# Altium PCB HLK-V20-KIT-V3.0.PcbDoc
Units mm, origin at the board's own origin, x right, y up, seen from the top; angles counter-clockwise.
Board outline 30 x 34 mm, 2 copper layers (Top Layer, Bottom Layer); 25 components, 30 nets, 128 pads, 85 vias.
Unrouted connection lines stored in the file: 3.
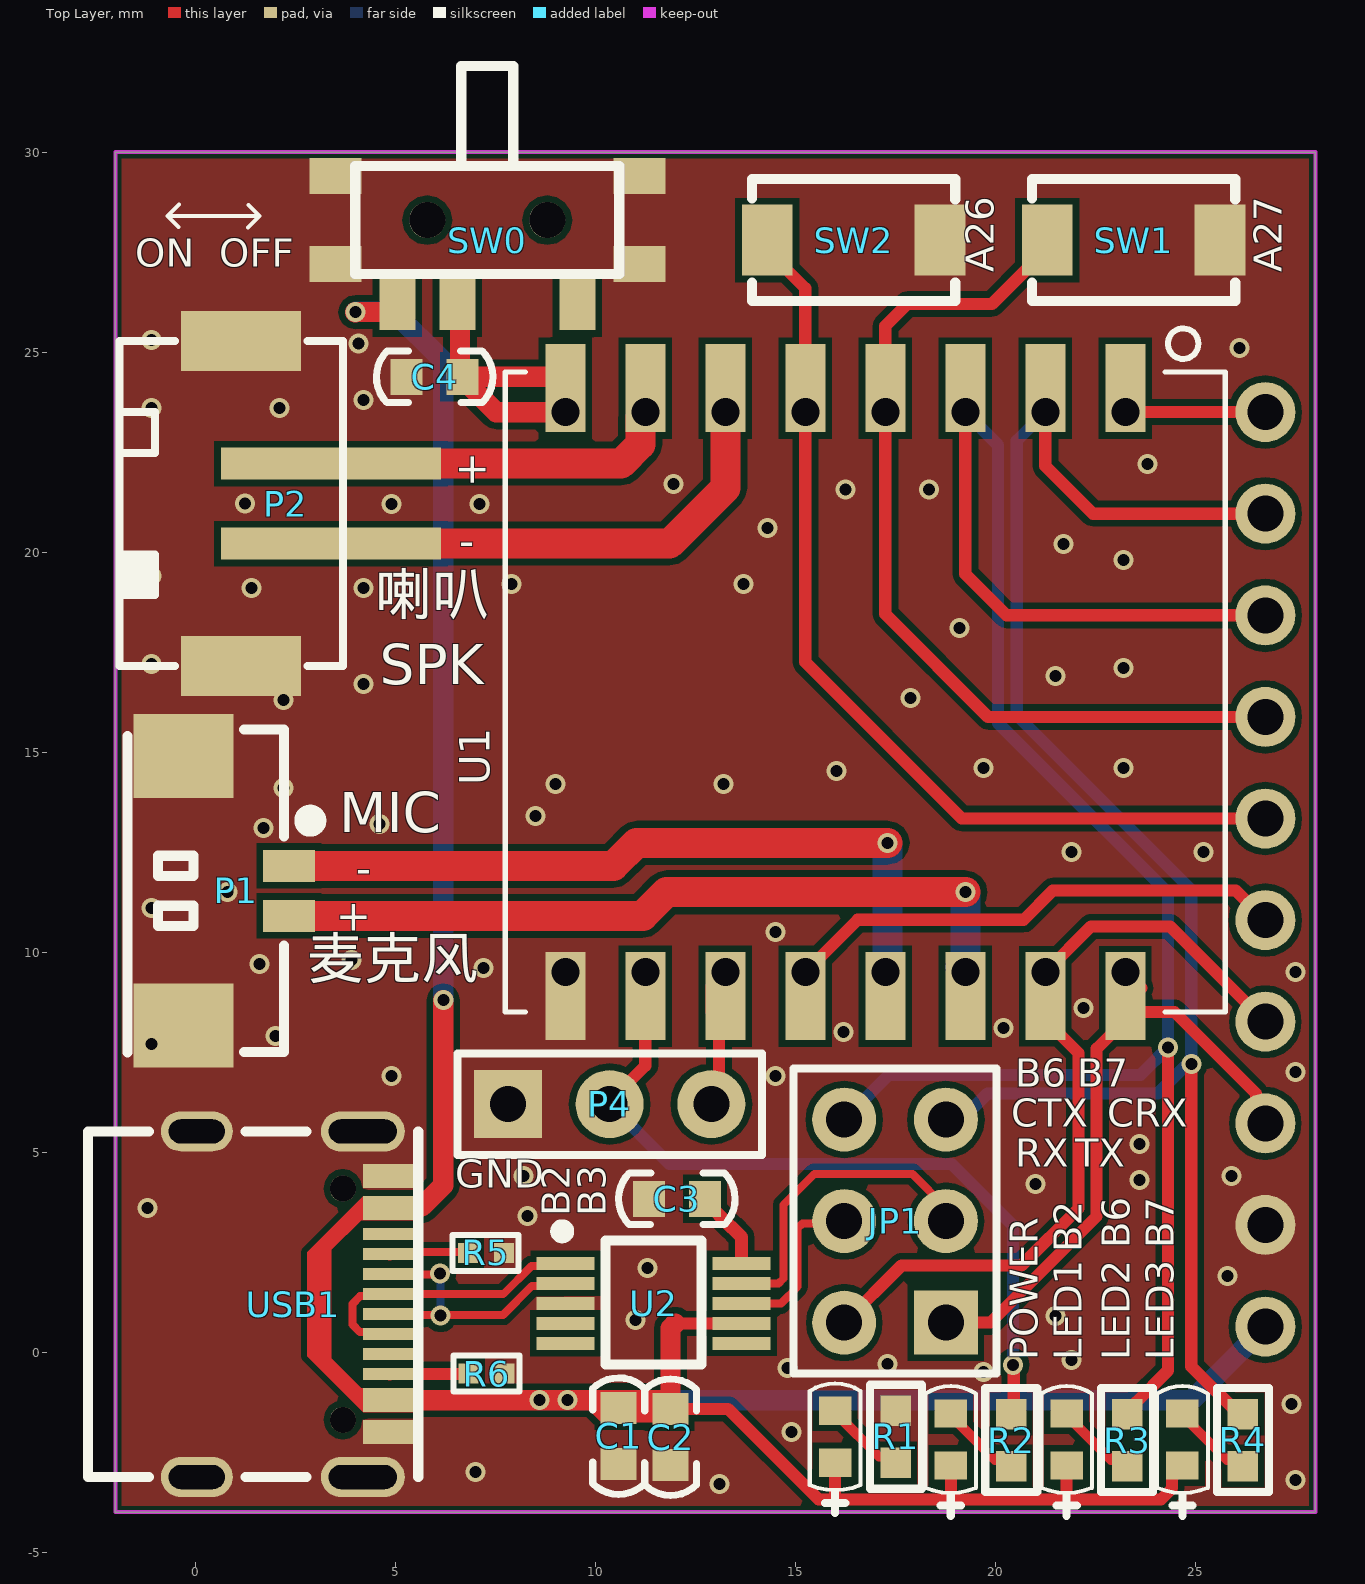
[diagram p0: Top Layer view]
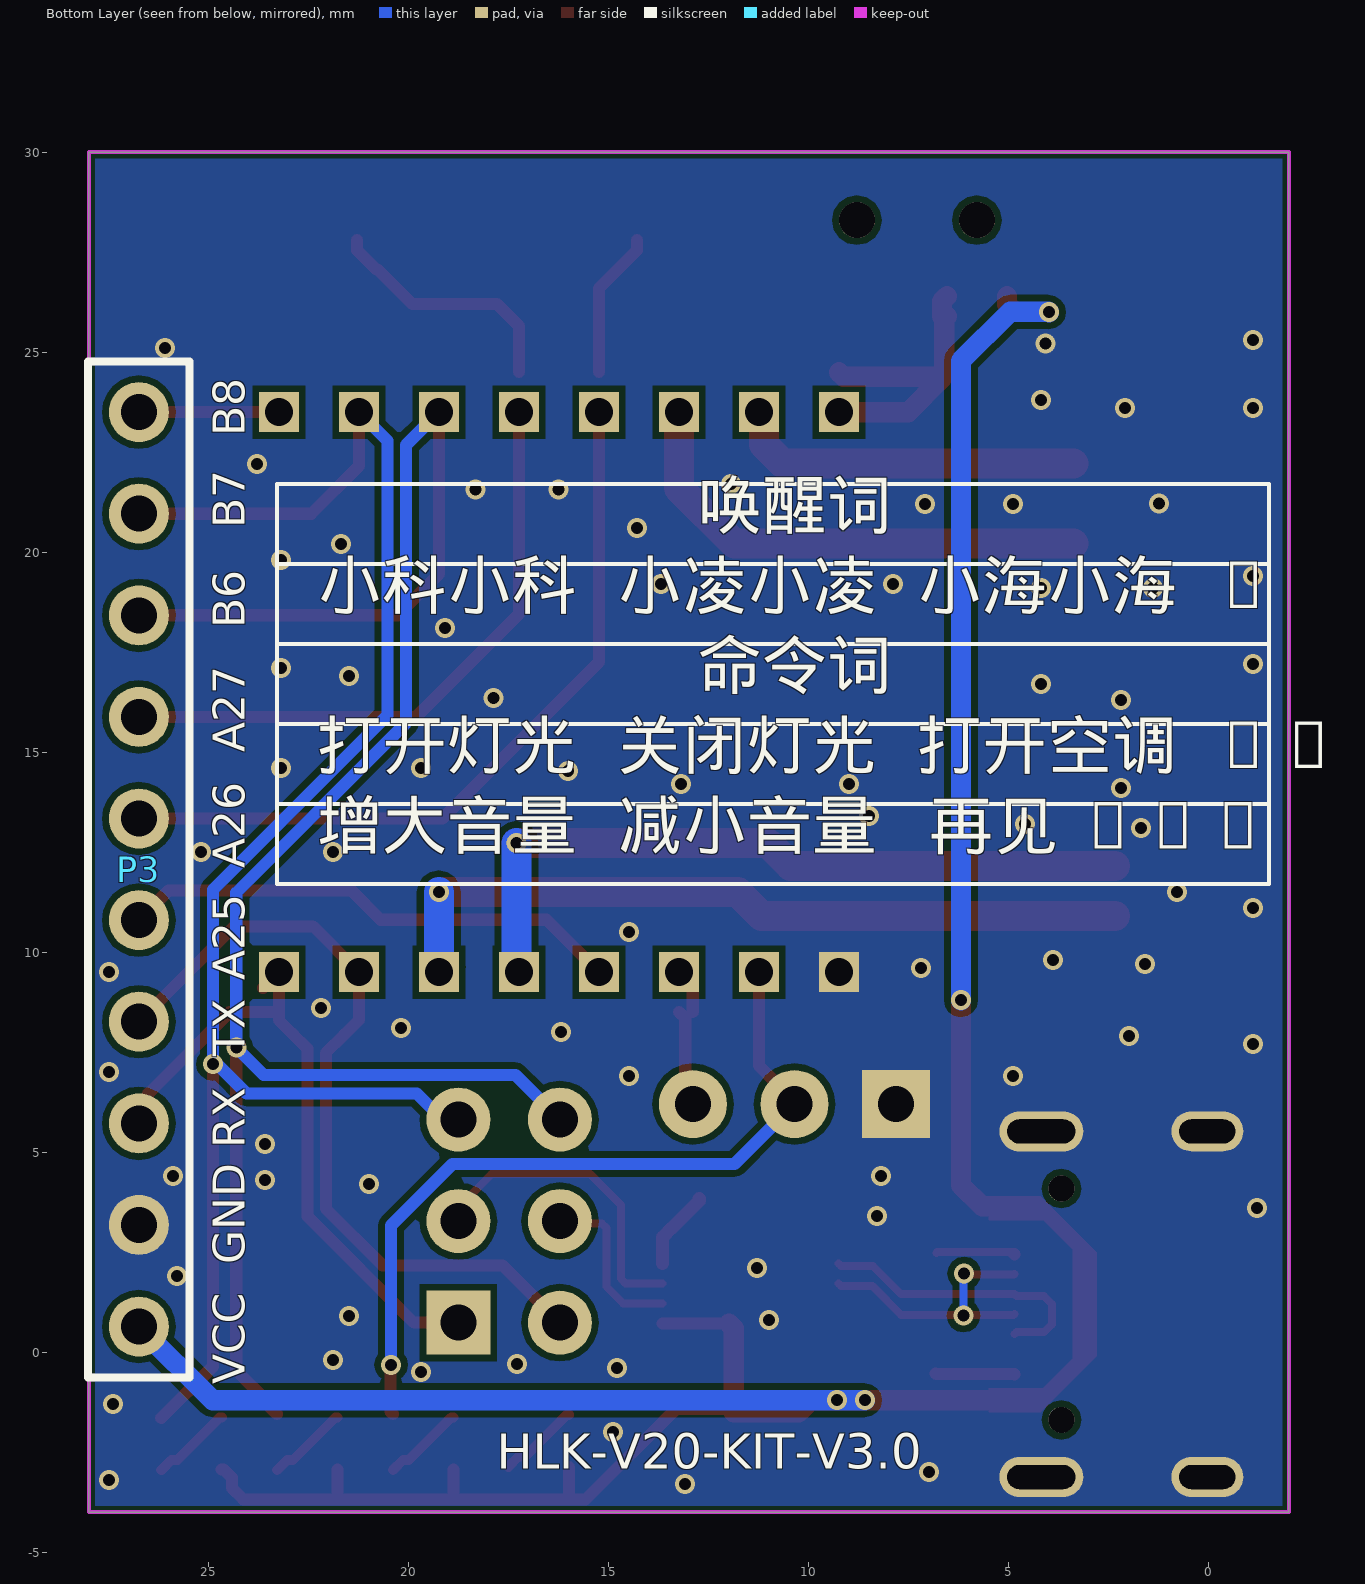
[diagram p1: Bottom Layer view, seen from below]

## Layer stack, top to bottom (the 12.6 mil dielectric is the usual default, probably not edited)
Top Solder: solder mask 0.0102, Solder Resist, Dk 3.5
Top Layer: signal copper 0.0356
Dielectric1: dielectric 0.32, FR-4, Dk 4.8
Bottom Layer: signal copper 0.0356
Bottom Solder: solder mask 0.0102, Solder Resist, Dk 3.5

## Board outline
-2,-4 -2,30 28,30 28,-4

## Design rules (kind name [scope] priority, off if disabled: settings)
Clearance Clearance_1 [OnLayer('Keep-Out Layer')] p1: gap=0.1 ignorepadtopadclearanceinfootprint=FALSE except(0: Arc-Hole Track-Hole SMDPad-Hole THPad-Hole Via-Hole Fill-Hole Poly-Hole Region-Hole Text-Hole)
Clearance [All] p2: gap=0.16 ignorepadtopadclearanceinfootprint=FALSE
FabricationTestpoint [(IsPad And (OnTopLayer Or OnBottomLayer))] p1: side=3 testpointundercomponent=TRUE minsize=1.016 maxsize=2.54 preferedsize=1.524 minholesize=0 maxholesize=1.016 preferedholesize=0.813 testpointgrid=0.025 allowsidetop=TRUE allowsidebottom=TRUE usegrid=TRUE gridtolerance=0
PlaneConnect [All] p1: planeconnectstyle=Direct reliefexpansion=0.508 reliefentries=4 reliefconductorwidth=0.254 reliefairgap=0.254
PolygonConnect [All] p1: connectstyle=Direct reliefconductorwidth=0.254 reliefentries=4 polygonreliefangle="90 Angle" airgapwidth=0.254
RoutingVias [All] p1: holewidth=0.3 width=0.5 viastyle="Through Hole" minholewidth=0.3 minwidth=0.5 maxholewidth=0.3 maxwidth=0.7
SolderMaskExpansion [All] p1: expansion=0.102 istentingtop=FALSE
Width [All] p1: maxlimit=5 minlimit=0.18 preferedwidth=0.254
28 further rules are at their usual default settings.

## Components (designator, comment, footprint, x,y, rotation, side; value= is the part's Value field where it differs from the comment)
C1 "4.7UF" "C 0603_L" 10.584,-2.097 r90 top
C2 "0.1UF" "C 0603_L" 11.883,-2.124 r90 top
C3 "0.1UF" "C 0603_L" 12.043,3.833 r0 top
C4 "0.1UF" "C 0603_L" 5.987,24.382 r0 top
JP1 "Header3X2" HDR2.54-LI-2x3P 17.494,3.275 r90 top
LED1 "LED" "LED 0603B-L" 18.878,-2.182 r90 top
LED2 "LED" "LED 0603B-L" 21.774,-2.182 r90 top
LED3 "LED" "LED 0603B-L" 24.67,-2.182 r90 top
P1 "1.25*2_SMT" "MX 1.25-LS-2P" 0.081,11.518 r270 top
P2 "1.25*2_SMT" PH2.0-LS-2P 0.895,21.211 r90 top
P3 "2.54*10" HDR1X10 26.75,23.5 r270 bottom locked
P4 "2.54*3" HDR2.54-LI-3P 10.36,6.2 r0 top
POWER "LED" "LED 0603B-L" 15.987,-2.114 r90 top
R1 "Res1" "R 0603_L" 17.514,-2.114 r90 top value=1k
R2 "Res1" "R 0603_L" 20.4,-2.2 r90 top value=1k
R3 "Res1" "R 0603_L" 23.296,-2.2 r90 top value=1k
R4 "Res1" "R 0603_L" 26.192,-2.2 r90 top value=1k
R5 "5.1K" "R 0402_L" 7.285,2.482 r180 top
R6 "5.1K" "R 0402_L" 7.304,-0.533 r180 top
SW0 "TA-3524A-A3" SW-SMD_3P-L6.6-W2.7-P1.50 7.3,27.8 r180 top
SW1 "3x6x5" KEY-K2 21.3,27.8 r0 top
SW2 "3x6x5" KEY-K2 14.3,27.8 r0 top
U1 "HLK-V20" HLK-V20 23.25,24.5 r270 top
U2 "CH340E" MSOP-10 11.459,1.217 r270 top
USB1 "USB_TYPE_C_16Pin" USB-C-16PIN-1 4.127,5.551 r270 top

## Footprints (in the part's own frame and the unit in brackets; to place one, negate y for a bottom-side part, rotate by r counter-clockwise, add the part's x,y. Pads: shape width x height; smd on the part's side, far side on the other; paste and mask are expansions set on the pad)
"C 0603_L" [mm]
  rect 0.8x0.9 smd: 1(-0.7,0) 2(0.7,0)
  silkscreen extent -1.46,-0.64 1.45,0.65, body extent -0.83,-0.39 0.8,0.43, height 0.81
HDR1X10 [mm]
  round 1.5 hole 0.9: 1(0,0) 2(2.54,0) 3(5.08,0) 4(7.62,0) 5(10.16,0) 6(12.7,0) 7(15.24,0) 8(17.78,0) 9(20.32,0) 10(22.86,0)
  silkscreen extent -1.27,-1.27 24.13,1.27
HDR2.54-LI-2x3P [mm] "双排排针，3x2脚"
  rect 1.6x1.6 hole 0.9: 1(-2.54,-1.27)
  round 1.6 hole 0.9: 2(-2.54,1.27) 3(0,-1.27) 4(0,1.27) 5(2.54,-1.27) 6(2.54,1.27)
  silkscreen extent -3.81,-2.54 3.81,2.54, body extent -3.81,-2.54 3.81,2.54, height 8.5
HDR2.54-LI-3P [mm] "排针，3脚"
  rect 1.7x1.7 hole 0.9: 1(-2.54,0)
  round 1.7 hole 0.9: 2(0,0) 3(2.54,0)
  silkscreen extent -3.81,-1.27 3.81,1.27, body extent -3.81,-1.27 3.81,1.27, height 8.5
HLK-V20 [mm]
  rect 1.4x1 smd: 1(0,0) 2(0,-2) 3(0,-4) 4(0,-6) 5(0,-8) 6(0,-10) 7(0,-12) 8(0,-14) 9(16,-14) 10(16,-12) 11(16,-10) 12(16,-8) 13(16,-6) 14(16,-4) 15(16,-2) 16(16,0)
  rect 1x1 hole 0.7: 1(1,0) 2(1,-2) 3(1,-4) 4(1,-6) 5(1,-8) 6(1,-10) 7(1,-12) 8(1,-14) 9(15,-14) 10(15,-12) 11(15,-10) 12(15,-8) 13(15,-6) 14(15,-4) 15(15,-2) 16(15,0)
  silkscreen extent -1.09,-15.5 16,2.5
KEY-K2 [mil] "正按小龟"
  rect 50x70 smd: 1(0,0) 2(170,0)
  silkscreen extent -15,-60 185,60, body extent -13,-58 183,60, height 79
"LED 0603B-L" [mil]
  rect 28x32 smd: 1(-25.67,-0.39) 2(25.51,-0.39)
  silkscreen extent -75,-25 52,25, body extent -31,-16 32,16, height 24
MSOP-10 [mm]
  rect 0.33x1.45 smd: 1(-1,-2.2) 2(-0.5,-2.2) 3(0,-2.2) 4(0.5,-2.2) 5(1,-2.2) 6(1,2.2) 7(0.5,2.2) 8(0,2.2) 9(-0.5,2.2) 10(-1,2.2)
  silkscreen extent -1.95,-2.44 1.53,1.2
"MX 1.25-LS-2P" [mm] "长：7.25m，宽：3.7mm，高：4.7mm"
  rect 2.1x2.5 smd: 0(-3.382,-0.381) 0(3.354,-0.381)
  rect 0.8x1.3 smd: 1(-0.639,2.261) 2(0.611,2.261)
  silkscreen extent -4.04,-1.78 4.02,2.99, body extent -3.83,-1.6 3.83,2.5, height 4.7
PH2.0-LS-2P [mm] "长：8mm，宽：5.5mm，高：6.1mm"
  rect 1.5x3 smd: 0(-4.064,-0.254) 0(4.064,-0.254)
  rect 0.8x5.5 smd: 1(-1,-2.492) 2(1,-2.492)
  silkscreen extent -4.06,-2.79 4.06,2.79, body extent -4,-5.05 4,2.75, height 6.15
"R 0402_L" [mm] "1/16W贴片电阻"
  rect 0.5x0.5 smd: 1(-0.431,0.004) 2(0.469,0.004)
  silkscreen extent -0.8,-0.45 0.85,0.45, body extent -0.5,-0.25 0.5,0.25, height 0.3
"R 0603_L" [mil] "1/10W贴片电阻"
  rect 30x30 smd: 1(-25.59,0) 2(25.59,0)
  silkscreen extent -51,-26 51,26, body extent -31,-16 32,16, height 16
SW-SMD_3P-L6.6-W2.7-P1.50 [mm]
  rect 1.3x0.9 smd: 0(-3.8,-1.6) 0(-3.8,0.6) 0(3.8,-1.6) 0(3.8,0.6)
  rect 0.9x1.3 smd: 1(-2.25,1.6) 2(0.75,1.6) 3(2.25,1.6)
  round 0.9 hole 0.9 unplated: ""(-1.5,-0.5) ""(1.5,-0.5)
  silkscreen extent -3.3,-4.35 3.3,0.85
USB-C-16PIN-1 [mm]
  oval 1x2.099 hole 0.6 slot 1.7 at 90 deg: 1(0.034,0.061) 2(8.674,0.061)
  oval 1x1.799 hole 0.6 slot 1.4 at 90 deg: 3(0.034,-4.088) 4(8.674,-4.088)
  rect 0.6x1.35 smd: A1B12(1.154,0.736) A4B9(1.954,0.736) B1A12(7.554,0.736) B4A9(6.754,0.736)
  rect 0.3x1.35 smd: A5(3.104,0.736) A6(4.104,0.736) A7(4.604,0.736) A8(2.604,0.736) B5(6.104,0.736) B6(5.104,0.736) B7(3.604,0.736) B8(5.604,0.736)
  round 0.65 hole 0.65 unplated: ""(1.464,-0.438) ""(7.244,-0.438)
  silkscreen extent 0.04,-6.81 8.67,1.45, body extent -0.15,-6.75 8.79,0.83, height 3.25

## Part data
C1 C2 C3 C4: library part CAP, "Capacitor"
JP1: library part "Header 3X2", "3*2P接插件"
P1 P2: library part CON2, "Connector"
P3: library part "Header 10", "Header, 10-Pin"
P4: library part CON3, "Connector"
R1 R2 R3 R4: "Resistor"
R5 R6: library part R, "贴片电阻"
SW0: BOM_Manufacturer=Yuandi
SW1 SW2: library part "TSW 3x6", "3x6轻触开关"
U1: "HLK-V20语音模块"
USB1: "TYPE_C_16Pin"

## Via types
v1: diameter 0.5, hole 0.3, Top Layer to Bottom Layer, tented both sides, 85 vias

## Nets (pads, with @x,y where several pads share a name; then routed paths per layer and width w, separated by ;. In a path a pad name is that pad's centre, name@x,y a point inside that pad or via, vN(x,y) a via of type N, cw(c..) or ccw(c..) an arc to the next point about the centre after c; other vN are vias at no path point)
5V: C1.2 C2.2 LED1.1 LED2.1 LED3.1 P3.10 POWER.1 SW0.3 U2.7 USB1.A4B9 USB1.B4A9 | length 74.6
  Top Layer w0.3: C2.2 13.324,-1.424 15.582,-3.682 15.997,-3.682 ; 12,0.717 U2.7 ; POWER.1@15.997,-2.866 15.997,-3.682 ; LED1.1@18.888,-2.935 18.888,-3.682 ; LED2.1@21.784,-2.935 21.784,-3.682 ; LED3.1@24.68,-2.935 24.629,-2.935 24.424,-3.14 24.424,-3.403 24.145,-3.682 21.784,-3.682 ; 15.997,-3.682 18.888,-3.682 ; 18.888,-3.682 21.784,-3.682
  Top Layer w0.508: v1(4,26) 4.004,26.004 4.854,26.004 SW0.3 SW0.3@5.05,26.4 ; USB1.B4A9 9.953,-1.203 ; USB1.A4B9 4.91,3.643 5.67,3.643 6.2,4.173 v1(6.2,8.8) ; C2.2@11.883,-1.5 10.251,-1.5 9.953,-1.203 ; C2.2 C2.2@11.883,-1.203 ; 12,0.717 11.883,0.6 C2.2@11.883,-1.203 ; 9.953,-1.203 C2.2@11.883,-1.203
  Bottom Layer w0.508: v1(4,26) 4.012,26.012 4.968,26.012 6.2,24.779 v1(6.2,8.8) ; v1(8.6,-1.2) 24.91,-1.2 P3.10
  other v1: 9.3,-1.2
A25: P3.6 U1.12 | length 12.6
  Top Layer w0.305: U1.12@15.25,9.5 15.598,9.848 16.559,10.809 20.709,10.809 21.438,11.538 26.012,11.538 P3.6
A26: P3.5 SW2.1 U1.5 | length 23.1
  Top Layer w0.305: SW2.1 14.3,27.546 15.25,26.596 U1.5@15.25,24.5 ; U1.5@15.25,23.5 15.25,17.25 19.16,13.34 P3.5
A27: P3.4 SW1.1 U1.4 | length 21.9
  Top Layer w0.305: U1.4@17.25,23.5 17.25,18.45 19.82,15.88 P3.4 ; U1.4@17.25,24.5 17.25,25.65 17.8,26.2 19.915,26.2 20.778,27.063 20.817,27.063 21.3,27.546 SW1.1
B2: P4.2 R2.2 U1.10 | length 19.8
  Top Layer w0.305: P4.2 10.36,6.269 11.25,7.159 11.25,8.5 U1.10@11.25,9.5 ; R2.2 20.463,-1.488 20.463,-0.334 v1(20.446,-0.317)
  Bottom Layer w0.305: P4.2 11.858,4.702 18.91,4.702 20.446,3.166 v1(20.446,-0.317)
B3: P4.3 U1.11 | length 3.6
  Top Layer w0.305: P4.3 13.094,6.394 13.094,8.344 U1.11@13.25,8.5 ; U1.11@12.902,8.5 12.902,9.152 U1.11@13.25,9.5
B6: JP1.6 P3.3 R3.2 U1.3 | length 48.4
  Top Layer w0.305: U1.3@19.25,23.5 19.25,19.45 20.28,18.42 P3.3 ; R3.2 23.525,-1.321 23.525,-1.253 24.316,-0.461 v1(24.316,7.616)
  Bottom Layer w0.305: JP1.6 17.337,6.927 20.117,6.927 23.627,6.927 v1(24.316,7.616) 24.316,11.484 20.07,15.73 20.07,22.68 U1.3@19.25,23.5
B7: JP1.5 P3.2 R4.2 U1.2 | length 41.8
  Top Layer w0.305: U1.2@21.25,23.5 21.25,22.15 22.44,20.96 P3.2 ; v1(24.9,7.2) 24.9,-0.358 R4.2@26.192,-1.65
  Bottom Layer w0.305: JP1.5 19.012,6.063 19.405,6.063 19.805,6.462 24.062,6.462 24.9,7.3 24.9,11.557 20.535,15.923 20.535,22.785 U1.2@21.25,23.5
B8: P3.1 U1.1 | length 3.5
  Top Layer w0.305: U1.1@23.25,23.5 P3.1
CH_RX: JP1.3 U2.9 | length 8
  Top Layer w0.2: U2.9 14.583,1.717 14.7,1.834 14.7,3.678 15.475,4.453 17.93,4.453 18.764,3.619 JP1.3
CH_TX: JP1.4 U2.8 | length 4.3
  Top Layer w0.2: U2.8 14.643,1.217 15.06,1.634 15.06,3.1 15.177,3.217 16.166,3.217 JP1.4
CTS: U2.5
DM: U2.2 USB1.A7 USB1.B7 | length 7.1
  Top Layer w0.2: USB1.A7 4.883,0.927 6.118,0.927 v1(6.136,0.91) 6.157,0.931 7.692,0.931 8.413,1.652 9.194,1.652 U2.2 ; USB1.B7 4.87,1.941 6.092,1.941 v1(6.118,1.968)
  Bottom Layer w0.2: v1(6.118,1.968) 6.136,1.95 v1(6.136,0.91)
DP: U2.1 USB1.A6 USB1.B6 | length 7.3
  Top Layer w0.2: USB1.B6 4.814,0.497 4.121,0.497 3.929,0.69 3.929,1.205 4.121,1.397 4.814,1.397 USB1.A6 7.699,1.447 8.404,2.152 9.194,2.152 U2.1
GND: C1.1 C2.1 C3.1 C4.1 P1.0 P2.0 P3.9 P4.1 R1.2 R5.1 R6.1 SW0.0 SW1.2 SW2.2 U1.9 U2.3 USB1.1 USB1.2 USB1.3 USB1.4 USB1.A1B12 USB1.B1A12
  other v1: 13.1,-3.3 27.5,-3.2 7,-3 14.9,-2 27.4,-1.3 19.7,-0.5 14.8,-0.4 17.3,-0.3 21.9,-0.2 11,0.8 21.5,0.9 25.8,1.9 11.3,2.1 8.3,3.4 -1.2,3.6 21,4.2 23.6,4.3 8.2,4.4 25.9,4.4 23.6,5.2 4.9,6.9 14.5,6.9 27.5,7 -1.1,7.7 2,7.9 16.2,8 20.2,8.1 22.2,8.6 27.5,9.5 7.2,9.6 1.6,9.7 3.9,9.8 14.5,10.5 -1.1,11.1 0.8,11.5 21.9,12.5 25.2,12.5 1.7,13.1 4.6,13.2 8.5,13.4 2.2,14.1 9,14.2 13.2,14.2 16.027,14.529 19.7,14.6 23.2,14.6 2.2,16.3 17.882,16.358 4.2,16.7 21.5,16.9 23.2,17.1 -1.1,17.2 19.1,18.1 1.4,19.1 4.2,19.1 7.9,19.2 13.7,19.2 -1.1,19.4 23.2,19.8 21.7,20.2 14.3,20.6 1.245,21.211 4.9,21.2 7.1,21.2 16.256,21.565 18.339,21.565 11.95,21.7 23.8,22.2 -1.1,23.6 2.1,23.6 4.2,23.8 26.1,25.1 4.085,25.217 -1.1,25.3
MIC+: P1.2 U1.14 | length 19.3
  Top Layer w0.75: P1.2 11.189,10.907 11.779,11.497 v1(19.254,11.497)
  Bottom Layer w0.75: U1.14@19.25,9.5 19.124,9.626 19.254,9.757 v1(19.254,11.497)
MIC-: P1.1 U1.13 | length 18.5
  Top Layer w0.75: P1.1 10.457,12.157 11.033,12.733 v1(17.311,12.733)
  Bottom Layer w0.75: U1.13@17.25,9.5 17.194,9.556 17.311,9.673 v1(17.311,12.733)
NetC3_2: C3.2 U2.10 | length 2
  Top Layer w0.33: C3.2 12.743,3.783 13.416,3.111 13.425,3.111 13.659,2.877 U2.10
NetLED1_2: LED1.2 R2.1 | length 2.1
  Top Layer w0.254: LED1.2@18.888,-1.635 18.939,-1.635 20,-2.696 20.146,-2.696 R2.1@20.4,-2.95
NetLED2_2: LED2.2 R3.1 | length 2.1
  Top Layer w0.254: LED2.2@21.784,-1.635 21.835,-1.635 22.896,-2.696 23.042,-2.696 R3.1@23.296,-2.95
NetLED3_2: LED3.2 R4.1 | length 2.1
  Top Layer w0.254: LED3.2@24.68,-1.635 24.731,-1.635 25.792,-2.696 25.938,-2.696 R4.1@26.192,-2.95
NetPOWER_2: POWER.2 R1.1 | length 2.1
  Top Layer w0.254: POWER.2@15.997,-1.566 16.048,-1.566 17.092,-2.61 17.26,-2.61 R1.1@17.514,-2.864
NetR5_2: R5.2 USB1.A5 | length 2
  Top Layer w0.2: USB1.A5@4.866,2.45 4.915,2.499 6.795,2.499 R5.2
  Top Layer w0.305: USB1.A5 USB1.A5@4.866,2.45
NetR6_2: R6.2 USB1.B5 | length 2
  Top Layer w0.305: USB1.B5 4.866,-0.55 6.821,-0.55 R6.2
RTS: U2.4
RX: JP1.2 P3.7 U1.15 | length 20.3
  Top Layer w0.3: JP1.2 17.654,2.165 20.654,2.165 22.076,3.586 22.076,7.482 21.608,7.95 21.6,7.95 21.25,8.3 21.25,8.5 21.25,9.5 22.393,10.643 24.367,10.643 P3.7
SPK+: P2.2 U1.7 | length 8.8
  Top Layer w0.75: P2.2 10.647,22.211 11.125,22.689 11.125,23.375 U1.7@11.25,23.5
SPK-: P2.1 U1.6 | length 12.3
  Top Layer w0.75: P2.1 11.861,20.211 13.25,21.6 U1.6@13.25,23.5
TX: JP1.1 P3.8 U1.16 | length 16.8
  Top Layer w0.3: JP1.1 19.875,0.735 22.536,3.396 22.536,7.586 22.9,7.95 23.25,8.3 U1.16@23.25,8.5 ; U1.16@23.65,9.1 23.25,9.5 U1.16@23.25,8.5 ; P3.8 26.52,5.95 26.52,6.464 24.484,8.5 U1.16@23.25,8.5
VCC: C4.2 SW0.2 U1.8 | length 7.6
  Top Layer w0.508: SW0.2@6.55,25.9 6.618,25.832 6.618,24.45 C4.2 9.132,24.382 U1.8@9.25,24.5 ; SW0.2@6.55,26.4 6.675,26.275 SW0.2@6.675,25.9 ; C4.2@6.687,24.332 7.519,23.5 U1.8@9.25,23.5
pads on no net: SW0. SW0.1 U2.6 USB1. USB1.A8 USB1.B8

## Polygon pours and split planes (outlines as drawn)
GND on Top Layer "MidLayer1-No Net" (solid, remove dead copper, pour order 4): -2,-4 28,-4 28,30 -2,30
GND on Bottom Layer "MidLayer1-No Net" (solid, remove dead copper, pour order 6): -2,-4 28,-4 28,30 -2,30

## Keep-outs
Keep-Out Layer:
  the board outline again, w0.1

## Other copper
Top Layer:
  region net 5V: 5.5,3.9 4.2,3.9 2.8,2.5 2.8,-0.1 4.2,-1.5 5.5,-1.5 5.5,-0.9 4.149,-0.9 3.4,-0.151 3.4,2.556 4.144,3.3 5.5,3.3

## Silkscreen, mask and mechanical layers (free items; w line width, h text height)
Top Overlay:
  lines w0.1: -0.425,28.125 -0.7,28.4 ; -0.412,28.688 -0.7,28.4 ; 0.425,28.4 -0.7,28.4 ; 0.475,28.4 1.6,28.4 ; 1.312,28.112 1.6,28.4 ; 1.325,28.675 1.6,28.4
  text "A26" at 20.2,27 h1.2 r90
  text "A27" at 27.4,27 h1.2 r90
  text "ON" at -1.5,26.9 h1.2
  text "OFF" at 0.6,26.9 h1.2
  text "+" at 6.6,22.5 h0.76 r270
  text "-" at 6.6,19.9 h0.76
  text "喇叭" at 4.5,18.1 h1.78
  text "SPK" at 4.615,16.696 h1
  text "MIC" at 3.6,13 h1
  text "-" at 4.4,12.3 h0.76 r180
  text "+" at 4.4,11.2 h0.76 r180
  text "麦克风" at 2.8,9 h1.78
  text "B6" at 20.5,6.4 h1.2
  text "B7" at 22.049,6.397 h1.2
  text "CTX" at 20.4,5.4 h1.2
  text "CRX" at 22.8,5.4 h1.2
  text "RX" at 20.5,4.4 h1.2
  text "TX" at 22,4.4 h1.2
  text "GND" at 6.498,3.875 h1.2
  text "B2" at 9.6,3.4 h1.2 r90
  text "B3" at 10.5,3.4 h1.2 r90
  text "B6" at 23.6,2.6 h1.2 r90
  text "B7" at 24.7,2.6 h1.2 r90
  text "B2" at 22.4,2.5 h1.2 r90
Bottom Overlay:
  lines w0.102: -1.5,13.707 23.297,13.707 ; -1.5,15.707 23.297,15.707 ; -1.5,17.707 23.297,17.707 ; -1.5,19.707 23.297,19.707 ; -1.5,11.707 -1.5,21.707 23.297,21.707 23.297,11.707 -1.5,11.707
  text "B8" at 24.1,22.9 h0.8 r270
  text "B7" at 24.1,20.6 h0.8 r270
  text "唤醒词" at 12.797,20.207 h2.03
  text "小海小海  …" at 7.297,18.207 h2.03
  text "小凌小凌" at 14.797,18.207 h2.03
  text "小科小科" at 22.297,18.207 h2.03
  text "B6" at 24.1,18.1 h0.8 r270
  text "命令词" at 12.797,16.207 h2.03
  text "A27" at 24.1,15 h0.8 r270
  text "打开空调  ..." at 7.297,14.207 h2.03
  text "关闭灯光" at 14.797,14.207 h2.03
  text "打开灯光" at 22.297,14.207 h2.03
  text "再见 ..." at 7,12.2 h2.03
  text "减小音量" at 14.797,12.207 h2.03
  text "增大音量" at 22.297,12.207 h2.03
  text "A26" at 24.1,12.1 h0.8 r270
  text "A25" at 24.1,9.3 h0.8 r270
  text "TX" at 24.1,7.4 h0.8 r270
  text "RX" at 24.1,5.1 h0.8 r270
  text "GND" at 24.1,2.2 h0.8 r270
  text "VCC" at 24.1,-0.8 h0.8 r270
  text "HLK-V20-KIT-V3.0" at 17.8,-3.2 h1.5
